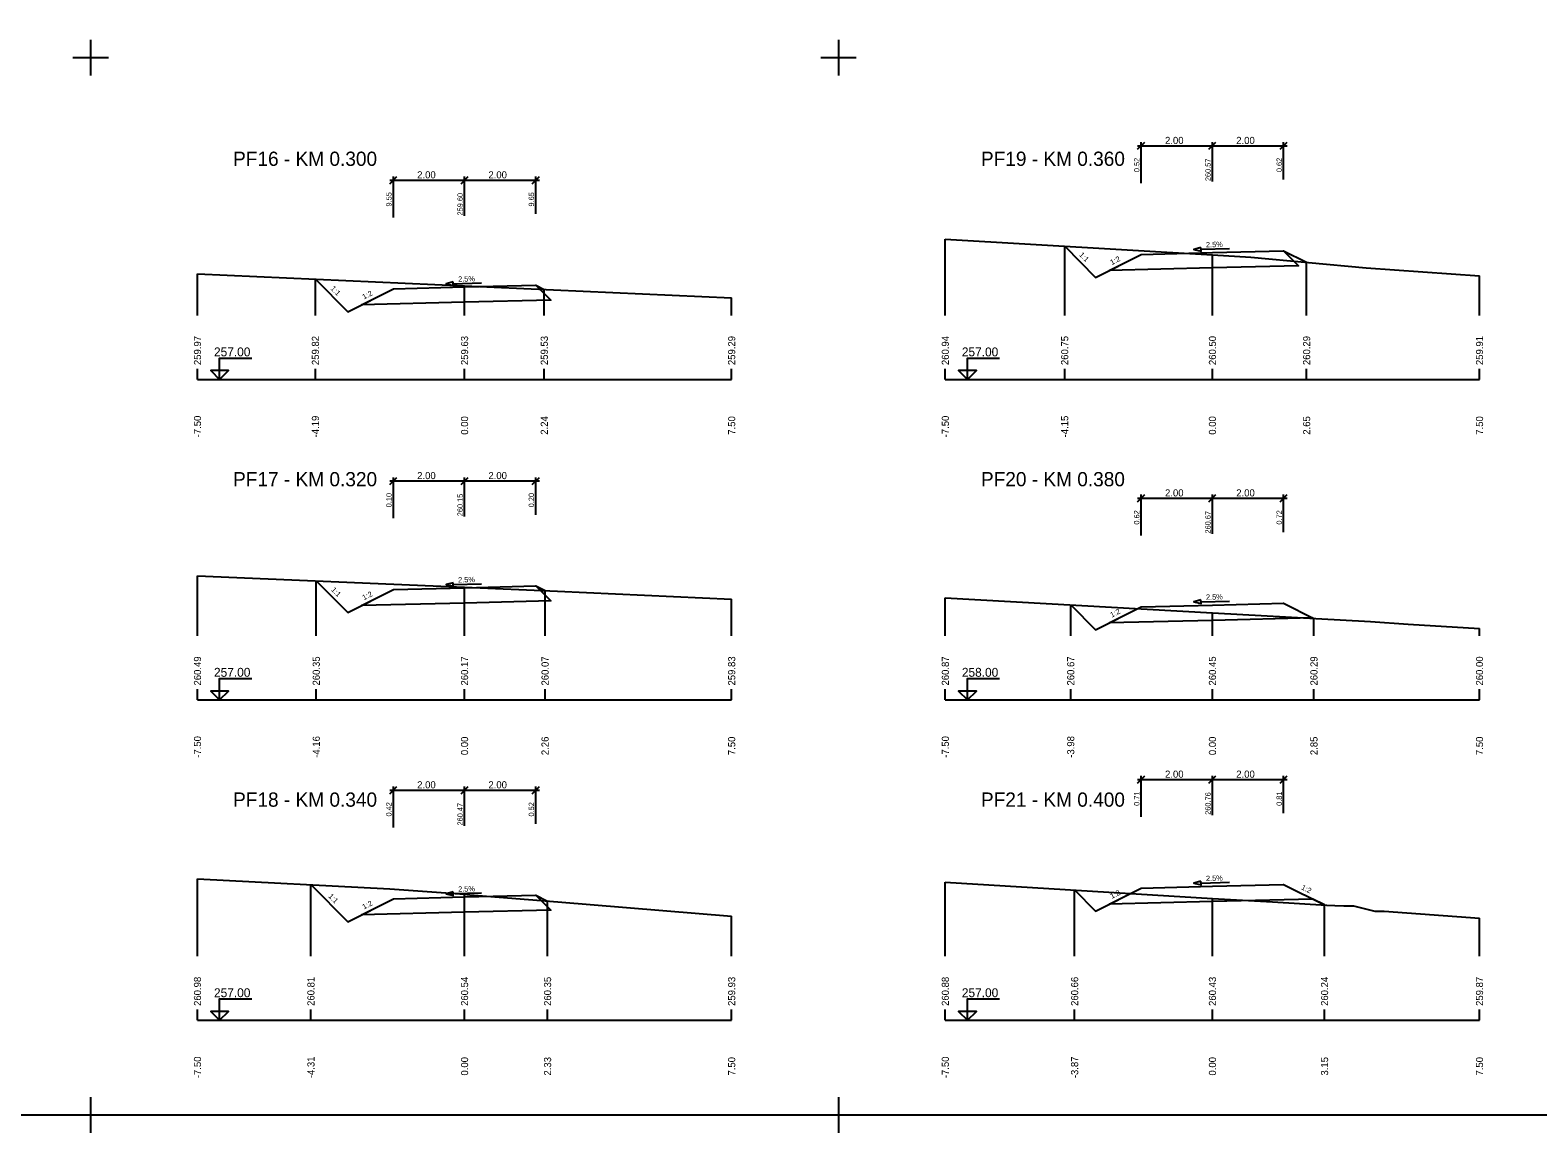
# Model space of a CAD drawing. Extents: x -5 to 1895, y -2 to 602.
# Drawn here: x 1033 to 1456.4, y -1.6 to 308.1 of the extents above; entities that cross this region are included whole.
import ezdxf

# ---------------------------------------------------------------- set-up
doc = ezdxf.new("R2010")
doc.units = 0
for name, color, linetype in [('KOTA', 7, 'Continuous'), ('KOTA_DELKY', 7, 'Continuous'), ('KOTA_DELKY_CONT', 7, 'Continuous'), ('NS_TELESO_VOZOVKY', 7, 'Continuous'), ('NS_V_PF', 7, 'Continuous'), ('REZY_PF_PUVODNI', 7, 'Continuous'), ('SESTAVY_REZU_PF', 7, 'Continuous'), ('SKLON', 7, 'Continuous'), ('SVK', 7, 'Continuous')]:
    doc.layers.add(name, color=color, linetype=linetype)

msp = doc.modelspace()

# ---------------------------------------------------------------- linework, layer by layer
for p, q in [((1050, 305.39), (1050, 295.39)), ((1050, 305.39), (1050, 295.39)), ((1050, 305.39), (1050, 295.39)), ((1050, 305.39), (1050, 295.39)), ((1050, 305.39), (1050, 295.39)), ((1050, 305.39), (1050, 295.39)), ((1050, 305.39), (1050, 295.39)), ((1050, 305.39), (1050, 295.39)), ((1050, 305.39), (1050, 295.39)), ((1050, 305.39), (1050, 295.39)), ((1050, 305.39), (1050, 295.39)), ((1050, 305.39), (1050, 295.39)), ((1050, 305.39), (1050, 295.39)), ((1050, 305.39), (1050, 295.39)), ((1050, 305.39), (1050, 295.39)), ((1050, 305.39), (1050, 295.39)), ((1050, 305.39), (1050, 295.39)), ((1050, 305.39), (1050, 295.39)), ((1050, 305.39), (1050, 295.39)), ((1050, 305.39), (1050, 295.39)), ((1050, 305.39), (1050, 295.39)), ((1050, 305.39), (1050, 295.39)), ((1050, 305.39), (1050, 295.39)), ((1050, 305.39), (1050, 295.39)), ((1050, 305.39), (1050, 295.39)), ((1050, 305.39), (1050, 295.39)), ((1050, 305.39), (1050, 295.39)), ((1050, 305.39), (1050, 295.39)), ((1050, 305.39), (1050, 295.39)), ((1050, 305.39), (1050, 295.39)), ((1260, 305.39), (1260, 295.39)), ((1260, 305.39), (1260, 295.39)), ((1260, 305.39), (1260, 295.39)), ((1260, 305.39), (1260, 295.39)), ((1260, 305.39), (1260, 295.39)), ((1260, 305.39), (1260, 295.39)), ((1260, 305.39), (1260, 295.39)), ((1260, 305.39), (1260, 295.39)), ((1260, 305.39), (1260, 295.39)), ((1260, 305.39), (1260, 295.39)), ((1260, 305.39), (1260, 295.39)), ((1260, 305.39), (1260, 295.39)), ((1260, 305.39), (1260, 295.39)), ((1260, 305.39), (1260, 295.39)), ((1260, 305.39), (1260, 295.39)), ((1260, 305.39), (1260, 295.39)), ((1260, 305.39), (1260, 295.39)), ((1260, 305.39), (1260, 295.39)), ((1260, 305.39), (1260, 295.39)), ((1260, 305.39), (1260, 295.39)), ((1260, 305.39), (1260, 295.39)), ((1260, 305.39), (1260, 295.39)), ((1260, 305.39), (1260, 295.39)), ((1260, 305.39), (1260, 295.39)), ((1260, 305.39), (1260, 295.39)), ((1260, 305.39), (1260, 295.39)), ((1260, 305.39), (1260, 295.39)), ((1260, 305.39), (1260, 295.39)), ((1260, 305.39), (1260, 295.39)), ((1260, 305.39), (1260, 295.39)), ((1055, 300.39), (1045, 300.39)), ((1055, 300.39), (1045, 300.39)), ((1055, 300.39), (1045, 300.39)), ((1055, 300.39), (1045, 300.39)), ((1055, 300.39), (1045, 300.39)), ((1055, 300.39), (1045, 300.39)), ((1055, 300.39), (1045, 300.39)), ((1055, 300.39), (1045, 300.39)), ((1055, 300.39), (1045, 300.39)), ((1055, 300.39), (1045, 300.39)), ((1055, 300.39), (1045, 300.39)), ((1055, 300.39), (1045, 300.39)), ((1055, 300.39), (1045, 300.39)), ((1055, 300.39), (1045, 300.39)), ((1055, 300.39), (1045, 300.39)), ((1055, 300.39), (1045, 300.39)), ((1055, 300.39), (1045, 300.39)), ((1055, 300.39), (1045, 300.39)), ((1055, 300.39), (1045, 300.39)), ((1055, 300.39), (1045, 300.39)), ((1055, 300.39), (1045, 300.39)), ((1055, 300.39), (1045, 300.39)), ((1055, 300.39), (1045, 300.39)), ((1055, 300.39), (1045, 300.39)), ((1055, 300.39), (1045, 300.39)), ((1055, 300.39), (1045, 300.39)), ((1055, 300.39), (1045, 300.39)), ((1055, 300.39), (1045, 300.39)), ((1055, 300.39), (1045, 300.39)), ((1055, 300.39), (1045, 300.39)), ((1265, 300.39), (1255, 300.39)), ((1265, 300.39), (1255, 300.39)), ((1265, 300.39), (1255, 300.39)), ((1265, 300.39), (1255, 300.39)), ((1265, 300.39), (1255, 300.39)), ((1265, 300.39), (1255, 300.39)), ((1265, 300.39), (1255, 300.39)), ((1265, 300.39), (1255, 300.39)), ((1265, 300.39), (1255, 300.39)), ((1265, 300.39), (1255, 300.39)), ((1265, 300.39), (1255, 300.39)), ((1265, 300.39), (1255, 300.39)), ((1265, 300.39), (1255, 300.39)), ((1265, 300.39), (1255, 300.39)), ((1265, 300.39), (1255, 300.39)), ((1265, 300.39), (1255, 300.39)), ((1265, 300.39), (1255, 300.39)), ((1265, 300.39), (1255, 300.39)), ((1265, 300.39), (1255, 300.39)), ((1265, 300.39), (1255, 300.39)), ((1265, 300.39), (1255, 300.39)), ((1265, 300.39), (1255, 300.39)), ((1265, 300.39), (1255, 300.39)), ((1265, 300.39), (1255, 300.39)), ((1265, 300.39), (1255, 300.39)), ((1265, 300.39), (1255, 300.39)), ((1265, 300.39), (1255, 300.39)), ((1265, 300.39), (1255, 300.39)), ((1265, 300.39), (1255, 300.39)), ((1265, 300.39), (1255, 300.39)), ((1050, 8.39), (1050, -1.61)), ((1050, 8.39), (1050, -1.61)), ((1050, 8.39), (1050, -1.61)), ((1050, 8.39), (1050, -1.61)), ((1050, 8.39), (1050, -1.61)), ((1050, 8.39), (1050, -1.61)), ((1050, 8.39), (1050, -1.61)), ((1050, 8.39), (1050, -1.61)), ((1050, 8.39), (1050, -1.61)), ((1050, 8.39), (1050, -1.61)), ((1050, 8.39), (1050, -1.61)), ((1050, 8.39), (1050, -1.61)), ((1260, 8.39), (1260, -1.61)), ((1260, 8.39), (1260, -1.61)), ((1260, 8.39), (1260, -1.61)), ((1260, 8.39), (1260, -1.61)), ((1260, 8.39), (1260, -1.61)), ((1260, 8.39), (1260, -1.61)), ((1260, 8.39), (1260, -1.61)), ((1260, 8.39), (1260, -1.61)), ((1260, 8.39), (1260, -1.61)), ((1260, 8.39), (1260, -1.61)), ((1260, 8.39), (1260, -1.61)), ((1260, 8.39), (1260, -1.61)), ((1055, 3.39), (1045, 3.39)), ((1055, 3.39), (1045, 3.39)), ((1055, 3.39), (1045, 3.39)), ((1055, 3.39), (1045, 3.39)), ((1055, 3.39), (1045, 3.39)), ((1055, 3.39), (1045, 3.39)), ((1055, 3.39), (1045, 3.39)), ((1055, 3.39), (1045, 3.39)), ((1055, 3.39), (1045, 3.39)), ((1055, 3.39), (1045, 3.39)), ((1055, 3.39), (1045, 3.39)), ((1055, 3.39), (1045, 3.39)), ((1265, 3.39), (1255, 3.39)), ((1265, 3.39), (1255, 3.39)), ((1265, 3.39), (1255, 3.39)), ((1265, 3.39), (1255, 3.39)), ((1265, 3.39), (1255, 3.39)), ((1265, 3.39), (1255, 3.39)), ((1265, 3.39), (1255, 3.39)), ((1265, 3.39), (1255, 3.39)), ((1265, 3.39), (1255, 3.39)), ((1265, 3.39), (1255, 3.39)), ((1265, 3.39), (1255, 3.39)), ((1265, 3.39), (1255, 3.39))]:
    msp.add_line(p, q)
msp.add_lwpolyline([(0, 597.39), (1890, 597.39), (1890, 3.39), (0, 3.39)], close=True)
at = {"layer": 'KOTA'}
for points in [[(1086.22, 212.5), (1083.72, 212.5), (1086.22, 210), (1086.22, 216), (1095.22, 216)], [(1296.22, 212.5), (1293.72, 212.5), (1296.22, 210), (1296.22, 216), (1305.22, 216)], [(1086.22, 210), (1088.72, 212.5), (1086.22, 212.5)], [(1296.22, 210), (1298.72, 212.5), (1296.22, 212.5)], [(1086.22, 122.5), (1083.72, 122.5), (1086.22, 120), (1086.22, 126), (1095.22, 126)], [(1296.22, 122.5), (1293.72, 122.5), (1296.22, 120), (1296.22, 126), (1305.22, 126)], [(1086.22, 120), (1088.72, 122.5), (1086.22, 122.5)], [(1296.22, 120), (1298.72, 122.5), (1296.22, 122.5)], [(1086.22, 32.5), (1083.72, 32.5), (1086.22, 30), (1086.22, 36), (1095.22, 36)], [(1296.22, 32.5), (1293.72, 32.5), (1296.22, 30), (1296.22, 36), (1305.22, 36)], [(1086.22, 30), (1088.72, 32.5), (1086.22, 32.5)], [(1296.22, 30), (1298.72, 32.5), (1296.22, 32.5)]]:
    msp.add_lwpolyline(points, dxfattribs=at)
at = {"layer": 'KOTA_DELKY'}
for points in [[(1344, 274.65), (1346, 276.65)], [(1344, 275.65), (1366, 275.65)], [(1345, 265.15), (1345, 276.65)], [(1364, 274.65), (1366, 276.65)], [(1364, 274.65), (1366, 276.65)], [(1364, 275.65), (1386, 275.65)], [(1365, 265.65), (1365, 276.65)], [(1365, 265.65), (1365, 276.65)], [(1384, 274.65), (1386, 276.65)], [(1385, 266.15), (1385, 276.65)], [(1134, 264.99), (1136, 266.99)], [(1135, 255.49), (1135, 266.99)], [(1154, 264.99), (1156, 266.99)], [(1154, 264.99), (1156, 266.99)], [(1155, 255.99), (1155, 266.99)], [(1155, 255.99), (1155, 266.99)], [(1174, 264.99), (1176, 266.99)], [(1175, 256.49), (1175, 266.99)], [(1134, 265.99), (1156, 265.99)], [(1154, 265.99), (1176, 265.99)], [(1134, 180.51), (1136, 182.51)], [(1135, 171.01), (1135, 182.51)], [(1154, 180.51), (1156, 182.51)], [(1154, 180.51), (1156, 182.51)], [(1155, 171.51), (1155, 182.51)], [(1155, 171.51), (1155, 182.51)], [(1174, 180.51), (1176, 182.51)], [(1175, 172.01), (1175, 182.51)], [(1134, 181.51), (1156, 181.51)], [(1154, 181.51), (1176, 181.51)], [(1344, 175.65), (1346, 177.65)], [(1344, 176.65), (1366, 176.65)], [(1345, 166.15), (1345, 177.65)], [(1364, 175.65), (1366, 177.65)], [(1364, 175.65), (1366, 177.65)], [(1364, 176.65), (1386, 176.65)], [(1365, 166.65), (1365, 177.65)], [(1365, 166.65), (1365, 177.65)], [(1384, 175.65), (1386, 177.65)], [(1385, 167.15), (1385, 177.65)], [(1344, 96.65), (1346, 98.65)], [(1344, 97.65), (1366, 97.65)], [(1345, 87.15), (1345, 98.65)], [(1364, 96.65), (1366, 98.65)], [(1364, 96.65), (1366, 98.65)], [(1364, 97.65), (1386, 97.65)], [(1365, 87.65), (1365, 98.65)], [(1365, 87.65), (1365, 98.65)], [(1384, 96.65), (1386, 98.65)], [(1385, 88.15), (1385, 98.65)], [(1134, 93.66), (1136, 95.66)], [(1134, 94.66), (1156, 94.66)], [(1135, 84.16), (1135, 95.66)], [(1154, 93.66), (1156, 95.66)], [(1154, 93.66), (1156, 95.66)], [(1154, 94.66), (1176, 94.66)], [(1155, 84.66), (1155, 95.66)], [(1155, 84.66), (1155, 95.66)], [(1174, 93.66), (1176, 95.66)], [(1175, 85.16), (1175, 95.66)]]:
    msp.add_lwpolyline(points, dxfattribs=at)
at = {"layer": 'NS_TELESO_VOZOVKY'}
for points in [[(1365, 245.65), (1385, 246.15), (1385, 246.15), (1389.2, 241.96), (1365, 241.35), (1336.05, 240.63), (1345, 245.15), (1345, 245.15), (1365, 245.65)], [(1155, 235.99), (1175, 236.49), (1175, 236.49), (1179.2, 232.3), (1155, 231.69), (1126.05, 230.97), (1135, 235.49), (1135, 235.49), (1155, 235.99)], [(1155, 151.51), (1175, 152.01), (1175, 152.01), (1179.2, 147.82), (1155, 147.21), (1126.05, 146.49), (1135, 151.01), (1135, 151.01), (1155, 151.51)], [(1365, 146.65), (1385, 147.15), (1385, 147.15), (1393.51, 142.9), (1393.19, 143.06), (1365, 142.35), (1336.05, 141.63), (1345, 146.15), (1345, 146.15), (1365, 146.65)], [(1365, 67.65), (1385, 68.15), (1385, 68.15), (1396.49, 62.4), (1393.19, 64.05), (1365, 63.35), (1336.05, 62.62), (1345, 67.15), (1345, 67.15), (1365, 67.65)], [(1155, 64.66), (1175, 65.16), (1175, 65.16), (1179.2, 60.96), (1155, 60.36), (1126.05, 59.63), (1135, 64.16), (1135, 64.16), (1155, 64.66)]]:
    msp.add_lwpolyline(points, dxfattribs=at)
at = {"layer": 'NS_V_PF'}
for points in [[(1323.51, 247.45), (1332.19, 238.68), (1345, 245.15), (1345, 245.15), (1365, 245.65), (1385, 246.15), (1385, 246.15), (1391.45, 242.93)], [(1113.11, 238.19), (1122.19, 229.02), (1135, 235.49), (1135, 235.49), (1155, 235.99), (1175, 236.49), (1175, 236.49), (1177.39, 235.3)], [(1113.36, 153.46), (1122.19, 144.54), (1135, 151.01), (1135, 151.01), (1155, 151.51), (1175, 152.01), (1175, 152.01), (1177.6, 150.71)], [(1325.21, 146.73), (1332.19, 139.67), (1345, 146.15), (1345, 146.15), (1365, 146.65), (1385, 147.15), (1385, 147.15), (1393.51, 142.9)], [(1111.86, 68.11), (1122.19, 57.68), (1135, 64.16), (1135, 64.16), (1155, 64.66), (1175, 65.16), (1175, 65.16), (1178.31, 63.5)], [(1326.31, 66.61), (1332.19, 60.67), (1345, 67.15), (1345, 67.15), (1365, 67.65), (1385, 68.15), (1385, 68.15), (1396.49, 62.4)]]:
    msp.add_lwpolyline(points, dxfattribs=at)
at = {"layer": 'REZY_PF_PUVODNI'}
for points in [[(1290, 249.44), (1365, 244.99), (1375.75, 244.35), (1408.2, 241.41), (1440, 239.09)], [(1080, 239.68), (1155, 236.3), (1230, 232.93)], [(1080, 154.88), (1155, 151.68), (1181.1, 150.56), (1230, 148.3)], [(1290, 148.71), (1365, 144.5), (1409.41, 142), (1419.95, 141.25), (1440, 140.04)], [(1080, 69.77), (1134, 66.96), (1155, 65.39), (1156.47, 65.28), (1181.15, 63.27), (1230, 59.28)], [(1290, 68.81), (1365, 64.26), (1381.84, 63.24), (1397.01, 62.37), (1397.09, 62.3), (1397.16, 62.37), (1399.36, 62.23), (1401.87, 62.2), (1404.63, 62.17), (1410.63, 60.66), (1413.23, 60.64), (1440, 58.68)]]:
    msp.add_lwpolyline(points, dxfattribs=at)
at = {"layer": 'SESTAVY_REZU_PF'}
for points in [[(1080, 210), (1230, 210)], [(1290, 210), (1440, 210)], [(1080, 120), (1230, 120)], [(1290, 120), (1440, 120)], [(1080, 30), (1230, 30)], [(1290, 30), (1440, 30)]]:
    msp.add_lwpolyline(points, dxfattribs=at)
at = {"layer": 'SKLON'}
for points in [[(1361.79, 247.07), (1359.8, 246.52), (1361.81, 246.07), (1361.79, 247.07)], [(1361.8, 246.57), (1369.8, 246.77)], [(1151.79, 237.41), (1149.8, 236.86), (1151.81, 236.41), (1151.79, 237.41)], [(1151.8, 236.91), (1159.8, 237.11)], [(1151.79, 152.93), (1149.8, 152.38), (1151.81, 151.93), (1151.79, 152.93)], [(1151.8, 152.43), (1159.8, 152.63)], [(1361.79, 148.07), (1359.8, 147.52), (1361.81, 147.07), (1361.79, 148.07)], [(1361.8, 147.57), (1369.8, 147.77)], [(1361.79, 69.07), (1359.8, 68.52), (1361.81, 68.07), (1361.79, 69.07)], [(1361.8, 68.57), (1369.8, 68.77)], [(1151.79, 66.08), (1149.8, 65.53), (1151.81, 65.08), (1151.79, 66.08)], [(1151.8, 65.58), (1159.8, 65.78)]]:
    msp.add_lwpolyline(points, dxfattribs=at)
at = {"layer": 'SVK'}
for points in [[(1290, 228), (1290, 249.44)], [(1323.51, 228), (1323.51, 247.45)], [(1365, 228), (1365, 244.99)], [(1391.45, 228), (1391.45, 242.93)], [(1080, 228), (1080, 239.68)], [(1113.11, 228), (1113.11, 238.19)], [(1440, 228), (1440, 239.09)], [(1155, 228), (1155, 236.3)], [(1177.39, 228), (1177.39, 235.3)], [(1230, 228), (1230, 232.93)], [(1080, 210), (1080, 213)], [(1113.11, 210), (1113.11, 213)], [(1155, 210), (1155, 213)], [(1177.39, 210), (1177.39, 213)], [(1230, 210), (1230, 213)], [(1290, 210), (1290, 213)], [(1323.51, 210), (1323.51, 213)], [(1365, 210), (1365, 213)], [(1391.45, 210), (1391.45, 213)], [(1440, 210), (1440, 213)], [(1080, 138), (1080, 154.88)], [(1113.36, 138), (1113.36, 153.46)], [(1155, 138), (1155, 151.68)], [(1177.6, 138), (1177.6, 150.71)], [(1230, 138), (1230, 148.3)], [(1290, 138), (1290, 148.71)], [(1325.21, 138), (1325.21, 146.73)], [(1365, 138), (1365, 144.5)], [(1393.51, 138), (1393.51, 142.9)], [(1440, 138), (1440, 140.04)], [(1080, 120), (1080, 123)], [(1113.36, 120), (1113.36, 123)], [(1155, 120), (1155, 123)], [(1177.6, 120), (1177.6, 123)], [(1230, 120), (1230, 123)], [(1290, 120), (1290, 123)], [(1325.21, 120), (1325.21, 123)], [(1365, 120), (1365, 123)], [(1393.51, 120), (1393.51, 123)], [(1440, 120), (1440, 123)], [(1080, 48), (1080, 69.77)], [(1111.86, 48), (1111.86, 68.11)], [(1290, 48), (1290, 68.81)], [(1155, 48), (1155, 65.39)], [(1326.31, 48), (1326.31, 66.61)], [(1365, 48), (1365, 64.26)], [(1178.31, 48), (1178.31, 63.5)], [(1230, 48), (1230, 59.28)], [(1396.49, 48), (1396.49, 62.4)], [(1440, 48), (1440, 58.68)], [(1080, 30), (1080, 33)], [(1111.86, 30), (1111.86, 33)], [(1155, 30), (1155, 33)], [(1178.31, 30), (1178.31, 33)], [(1230, 30), (1230, 33)], [(1290, 30), (1290, 33)], [(1326.31, 30), (1326.31, 33)], [(1365, 30), (1365, 33)], [(1396.49, 30), (1396.49, 33)], [(1440, 30), (1440, 33)]]:
    msp.add_lwpolyline(points, dxfattribs=at)

# ---------------------------------------------------------------- texts
at = {"layer": 'KOTA'}
for s, p in [('257.00', (1084.64, 216.5)), ('257.00', (1294.64, 216.5)), ('257.00', (1084.64, 126.5)), ('258.00', (1294.64, 126.5)), ('257.00', (1084.64, 36.5)), ('257.00', (1294.64, 36.5))]:
    msp.add_text(s, height=2.5, dxfattribs=at).set_placement(p)
at = {"layer": 'KOTA_DELKY'}
for p in [(1351.69, 276.15), (1371.69, 276.15), (1141.69, 266.49), (1161.69, 266.49), (1141.69, 182.01), (1161.69, 182.01), (1351.69, 177.15), (1371.69, 177.15), (1351.69, 98.15), (1371.69, 98.15), (1141.69, 95.16), (1161.69, 95.16)]:
    msp.add_text('2.00', height=2, dxfattribs=at).set_placement(p)
at = {"layer": 'KOTA_DELKY_CONT'}
for s, p in [('0.52', (1344.5, 268.24)), ('260.57', (1364.5, 265.73)), ('0.62', (1384.5, 268.24)), ('9.55', (1134.5, 258.58)), ('259.60', (1154.5, 256.07)), ('9.65', (1174.5, 258.58)), ('0.10', (1134.5, 174.1)), ('0.20', (1174.5, 174.1)), ('260.15', (1154.5, 171.59)), ('0.62', (1344.5, 169.24)), ('260.67', (1364.5, 166.73)), ('0.72', (1384.5, 169.24)), ('0.71', (1344.5, 90.24)), ('260.76', (1364.5, 87.72)), ('0.81', (1384.5, 90.24)), ('0.42', (1134.5, 87.25)), ('260.47', (1154.5, 84.73)), ('0.52', (1174.5, 87.25))]:
    msp.add_text(s, height=1.5, rotation=90, dxfattribs=at).set_placement(p)
at = {"layer": 'SESTAVY_REZU_PF'}
for s, p in [('PF16 - KM 0.300', (1090, 270)), ('PF19 - KM 0.360', (1300, 270)), ('PF17 - KM 0.320', (1090, 180)), ('PF20 - KM 0.380', (1300, 180)), ('PF18 - KM 0.340', (1090, 90)), ('PF21 - KM 0.400', (1300, 90))]:
    msp.add_text(s, height=4, dxfattribs=at).set_placement(p)
at = {"layer": 'SKLON'}
for s, rotation, p in [('1:1', 314.7121, (1327.45, 244.89)), ('2.5%', 1.4321, (1363.2, 247.11)), ('1:2', 26.8233, (1336.74, 242.1)), ('2.5%', 1.4321, (1153.2, 237.45)), ('1:1', 314.7121, (1117.25, 235.43)), ('1:2', 26.8233, (1126.74, 232.44)), ('2.5%', 1.4321, (1153.2, 152.97)), ('1:1', 314.7121, (1117.38, 150.82)), ('1:2', 26.8233, (1126.74, 147.96)), ('2.5%', 1.4321, (1363.2, 148.11)), ('1:2', 26.8233, (1336.74, 143.09)), ('2.5%', 1.4321, (1363.2, 69.1)), ('1:2', 333.4349, (1389.78, 66.87)), ('1:1', 314.7121, (1116.63, 64.72)), ('1:2', 26.8233, (1126.74, 61.1)), ('2.5%', 1.4321, (1153.2, 66.11)), ('1:2', 26.8233, (1336.74, 64.09))]:
    msp.add_text(s, height=1.5, rotation=rotation, dxfattribs=at).set_placement(p)
at = {"layer": 'SVK'}
for s, p in [(' 259.97', (1081, 213.3)), (' 259.82', (1114.11, 213.3)), (' 259.63', (1156, 213.3)), (' 259.53', (1178.39, 213.3)), (' 259.29', (1231, 213.3)), (' 260.94', (1291, 213.3)), (' 260.75', (1324.51, 213.3)), (' 260.50', (1366, 213.3)), (' 260.29', (1392.45, 213.3)), (' 259.91', (1441, 213.3)), (' -7.50', (1081, 193)), (' -4.19', (1114.11, 193)), ('  0.00', (1156, 193)), ('  2.24', (1178.39, 193)), ('  7.50', (1231, 193)), (' -7.50', (1291, 193)), (' -4.15', (1324.51, 193)), ('  0.00', (1366, 193)), ('  2.65', (1392.45, 193)), ('  7.50', (1441, 193)), (' 260.49', (1081, 123.3)), (' 260.35', (1114.36, 123.3)), (' 260.17', (1156, 123.3)), (' 260.07', (1178.6, 123.3)), (' 259.83', (1231, 123.3)), (' 260.87', (1291, 123.3)), (' 260.67', (1326.21, 123.3)), (' 260.45', (1366, 123.3)), (' 260.29', (1394.51, 123.3)), (' 260.00', (1441, 123.3)), (' -7.50', (1081, 103)), (' -4.16', (1114.36, 103)), ('  0.00', (1156, 103)), ('  2.26', (1178.6, 103)), ('  7.50', (1231, 103)), (' -7.50', (1291, 103)), (' -3.98', (1326.21, 103)), ('  0.00', (1366, 103)), ('  2.85', (1394.51, 103)), ('  7.50', (1441, 103)), (' 260.98', (1081, 33.3)), (' 260.81', (1112.86, 33.3)), (' 260.54', (1156, 33.3)), (' 260.35', (1179.31, 33.3)), (' 259.93', (1231, 33.3)), (' 260.88', (1291, 33.3)), (' 260.66', (1327.31, 33.3)), (' 260.43', (1366, 33.3)), (' 260.24', (1397.49, 33.3)), (' 259.87', (1441, 33.3)), (' -7.50', (1081, 13)), (' -4.31', (1112.86, 13)), ('  0.00', (1156, 13)), ('  2.33', (1179.31, 13)), ('  7.50', (1231, 13)), (' -7.50', (1291, 13)), (' -3.87', (1327.31, 13)), ('  0.00', (1366, 13)), ('  3.15', (1397.49, 13)), ('  7.50', (1441, 13))]:
    msp.add_text(s, height=2, rotation=90, dxfattribs=at).set_placement(p)

doc.saveas('drawing.dxf')
